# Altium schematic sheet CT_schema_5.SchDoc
size 145 x 108 mm
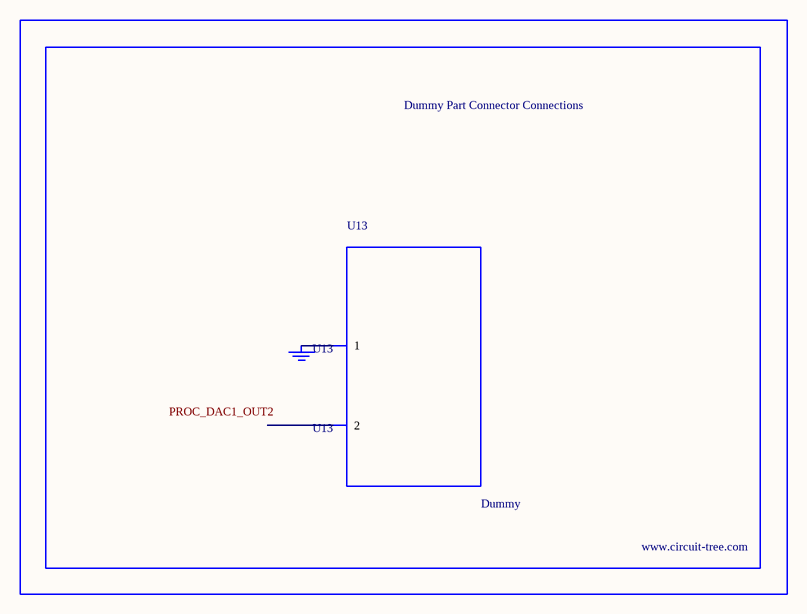
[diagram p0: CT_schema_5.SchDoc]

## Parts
BORDER4  (no value)
GND_INSTANCE_4_0  (no value)
U13  Dummy  [DUMMY_PACKAGE_140]

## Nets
NetGND_INSTANCE_4_0_0: GND_INSTANCE_4_0.0(GND) U13.1

Not connected (* = marked no-connect by the designer): U13 2

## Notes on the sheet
- Labels drawn without touching a wire or pin: PROC_DAC1_OUT2

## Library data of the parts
BORDER4 = BORDER_PAGE4
GND_INSTANCE_4_0 = GND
